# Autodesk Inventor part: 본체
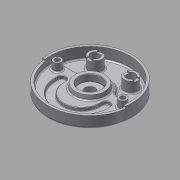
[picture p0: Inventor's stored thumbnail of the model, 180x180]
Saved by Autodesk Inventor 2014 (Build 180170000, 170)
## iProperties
Created: 2015-06
Part Number: 본체
Material: 알루미늄 6061
Document SubType Name: Modeling
Designer: MYHOME
Mass: 1071 g
Surface Area: 1034.49 cm^2
Volume: 395.202 cm^3
Density: 2.71 g/cm^3
Appearance: 알루미늄 - 평지
Author: MYHOME
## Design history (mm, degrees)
sketch "스케치1"
  geometry: C1 r 95 at (0, 0); 1 further point
  constraints: 1 centre point, 1 coincident
  dimensions: "d0" = 190 diameter of C1
extrude "돌출1" new body sketch "스케치1" distance "d1" = 32; taper "d2" = 0 deg
sketch "스케치2"
  geometry: C1 r 95 at (0, 0) reference; C2 r 90 at (0, 0)
  constraints: 1 centre point, 1 coincident
  dimensions: "d3" = 180 diameter of C2
extrude "돌출2" cut sketch "스케치2" distance "d4" = 18; taper "d5" = 0 deg
sketch "스케치3"
  geometry: L1 (0, 0)-(-95, 0); L2 (0, 0)-(-94.075, -13.221); L3 (0, 0)-(95, 0); L4 (0, 0)-(94.075, -13.221); A1 r 95 centre (0, 0) between (-95, 0) and (-94.075, -13.221) reference
  constraints: 8 end point, 4 point on circle, 1 collinear, 1 horizontal
  dimensions: "d6" = 8 deg angle of L1 L2; "d7" = 8 deg angle of L3 L4
extrude "돌출3" cut sketch "스케치3" distance "d8" = 5; taper "d9" = 0 deg
sketch "스케치4"
  geometry: L1 (-50, -24)-(-50, -14); L2 (-59, -19)-(-59, -14); L3 (-41, -14)-(-41, -19); L4 (50, -24)-(50, -14); L5 (41, -19)-(41, -14); L6 (59, -14)-(59, -19); C1 r 90 at (0, 0) reference; A1 r 50 centre (0, -19) between (-50, -19) and (50, -19); A2 r 59 centre (0, -19) between (-59, -19) and (59, -19); A3 r 41 centre (0, -19) between (-41, -19) and (41, -19); A4 r 9 centre (-50, -19) between (-41, -19) and (-59, -19); A5 r 9 centre (50, -19) between (59, -19) and (41, -19); A6 r 9 centre (-50, -14) between (-41, -14) and (-59, -14); A7 r 9 centre (50, -14) between (59, -14) and (41, -14); 2 further points
  constraints: 16 end point, 14 point on circle, 8 tangent, 7 centre point, 3 parallel, 2 coincident, 2 horizontal alignment, 2 midpoint, 1 vertical, 1 vertical alignment
  dimensions: "d10" = 19 distance of C1.centre A1.centre; "d11" = 41 radius of A3; "d12" = 59 radius of A2; "d19" = 5 distance of L4.end point (50, -19); "d21" = 5 distance of L1.end point (-50, -19)
extrude "돌출4" cut sketch "스케치4" distance "d23" = 7; taper "d24" = 0 deg
sketch "스케치6"
  geometry: C1 r 90 at (0, 0) reference; C2 r 35 at (0, 0)
  constraints: 1 centre point, 1 coincident
  dimensions: "d25" = 70 diameter of C2
extrude "돌출5" join sketch "스케치6" distance "d26" = 10; taper "d27" = -10 deg
sketch "스케치7"
  geometry: C1 r 33.237 at (0, 0) reference; C2 r 25 at (0, 0)
  constraints: 1 centre point, 1 coincident
  dimensions: "d28" = 50 diameter of C2
extrude "돌출6" cut sketch "스케치7" distance "d29" = 15; taper "d30" = 0 deg
sketch "스케치8"
  geometry: C1 r 95 at (0, 0) reference; C2 r 26 at (0, 0)
  constraints: 1 centre point, 1 coincident
  dimensions: "d31" = 52 diameter of C2
extrude "돌출7" join sketch "스케치8" distance "d32" = 12; taper "d33" = -15 deg
sketch "스케치9"
  geometry: C1 r 22.785 at (0, 0) reference; C2 r 11.5 at (0, 0)
  constraints: 1 centre point, 1 coincident
  dimensions: "d34" = 23 diameter of C2
extrude "돌출8" cut sketch "스케치9" stored distance "d35" = 12; taper "d36" = 0 deg
sketch "스케치10"
  geometry: L1 (38.833, 16)-(88.566, 16); L2 (-88.566, 16)-(-38.833, 16); C1 r 35 at (0, 0) reference; C2 r 42 at (0, 0); A1 r 90 centre (0, 0) between (-89.124, -12.526) and (89.124, -12.526) reference; A2 r 42 centre (0, 0) between (38.833, 16) and (-38.833, 16); A3 r 90 centre (0, 0) between (88.566, 16) and (-88.566, 16); A4 r 90 centre (0, 0) between (89.124, -12.526) and (-89.124, -12.526) reference
  constraints: 4 end point, 4 point on circle, 3 centre point, 3 concentric, 2 coincident, 1 collinear, 1 horizontal
  dimensions: "d37" = 84 diameter of C2; "d39" = 16 distance from line of C1.centre L2
extrude "돌출9" cut sketch "스케치10" distance "d40" = 7; taper "d41" = 0 deg
fillet "모깎기1" dims "d42" = 10
sketch "스케치14"
  geometry: C1 r 9 at (-74, 0); C2 r 9 at (74, 0); A1 r 90 centre (0, 0) between (-85.114, 29.25) and (85.114, 29.25) reference
  constraints: 2 centre point, 2 horizontal alignment
  dimensions: "d45" = 18 diameter of C1; "d46" = 18 diameter of C2; "d47" = 74 distance of A1.centre C1.centre; "d48" = 148 distance of C2.centre C1.centre
extrude "돌출10" join sketch "스케치14" stored distance "d49" = 7; taper "d50" = 0 deg
sketch "스케치16"
  geometry: C1 r 9 at (0, 0) reference; C2 r 5.5 at (0, 0); C3 r 9 at (148, 0) reference; C4 r 5.5 at (148, 0); 1 further point
  constraints: 2 centre point, 2 coincident
  dimensions: "d51" = 11 diameter of C2; "d52" = 11 diameter of C4
extrude "돌출11" cut sketch "스케치16" stored distance "d53" = 7; taper "d54" = 0 deg
sketch "스케치17"
  geometry: C1 r 5.5 at (74, 0) reference; C2 r 5.5 at (-74, 0) reference; C3 r 9 at (-74, 0); C4 r 9 at (74, 0)
  constraints: 2 centre point, 2 coincident
  dimensions: "d55" = 18 diameter of C3; "d56" = 18 diameter of C4
extrude "돌출12" cut sketch "스케치17" distance "d57" = 11; taper "d58" = 0 deg
sketch "스케치18"
  geometry: C1 r 15 at (-40, 52); C2 r 15 at (40, 52); A1 r 90 centre (0, 0) between (85.114, 29.25) and (-85.114, 29.25) reference
  constraints: 2 centre point
  dimensions: "d59" = 30 diameter of C1; "d60" = 30 diameter of C2; "d61" = 52 vertical distance of A1.centre C2.centre; "d62" = 52 vertical distance of A1.centre C1.centre; "d63" = 40 horizontal distance of A1.centre C1.centre; "d64" = 80 distance of C2.centre C1.centre
extrude "돌출13" join sketch "스케치18" stored distance "d65" = 11; taper "d66" = 0 deg
sketch "스케치19"
  geometry: C1 r 15 at (0, 0) reference; C2 r 15 at (80, 0) reference; C3 r 10 at (0, 0); C4 r 10 at (80, 0); 1 further point
  constraints: 2 centre point, 2 coincident
  dimensions: "d67" = 20 diameter of C4; "d68" = 20 diameter of C3
extrude "돌출14" cut sketch "스케치19" stored distance "d69" = 11; taper "d70" = 0 deg
sketch "스케치21"
  geometry: C1 r 95 at (0, 0) reference; C2 r 68 at (0, 0)
  constraints: 1 centre point, 1 coincident, 1 other
  dimensions: "d77" = 136 diameter of C2
feature "엠보싱1" sketch "스케치21" dims "d78" = 0.5, "d79" = 0
fillet "모깎기2" dims "d80" = 3
fillet "모깎기3" dims "d81" = 5
fillet "모깎기4" dims "d82" = 3
fillet "모깎기5" dims "d83" = 3
fillet "모깎기6" dims "d84" = 3
fillet "모깎기7" dims "d85" = 3
fillet "모깎기8" dims "d86" = 1
fillet "모깎기9" dims "d87" = 0.3
chamfer "모따기1" distance "d88" = 1; stored, may be unused: second distance "d89" = 2, angle "d90" = 45 deg
chamfer "모따기2" distance "d91" = 1; stored, may be unused: second distance "d92" = 2, angle "d93" = 45 deg
fillet "모깎기10" dims "d94" = 3
chamfer "모따기3" distance "d95" = 1; stored, may be unused: second distance "d96" = 2, angle "d97" = 45 deg
sketch "스케치23"
  geometry: L1 (-6, -20)-(6, -20); L2 (6, -20)-(6, 20); L3 (6, 20)-(-6, 20); L4 (-6, 20)-(-6, -20); L5 (-6, -20)-(6, 20); L6 (6, -20)-(-6, 20); L7 (100, -6)-(60, -6); L8 (60, -6)-(60, 6); L9 (60, 6)-(100, 6); L10 (100, 6)-(100, -6); L11 (100, -6)-(60, 6); L12 (60, -6)-(100, 6); C1 r 15 at (0, 0) reference; C2 r 15 at (80, 0) reference; 1 further point
  constraints: 24 end point, 4 midpoint, 4 parallel, 2 horizontal, 2 perpendicular
  dimensions: "d98" = 12 distance of L2.end L3.end; "d99" = 12 distance of L7.end L8.end; "d100" = 40 distance of L8.end L9.end; "d101" = 40 distance of L1.end L2.end
extrude "돌출16" cut sketch "스케치23" distance "d102" = 3; taper "d103" = 0 deg
node "솔리드1"
node "투영된 루프1"
node "투영된 루프2"
